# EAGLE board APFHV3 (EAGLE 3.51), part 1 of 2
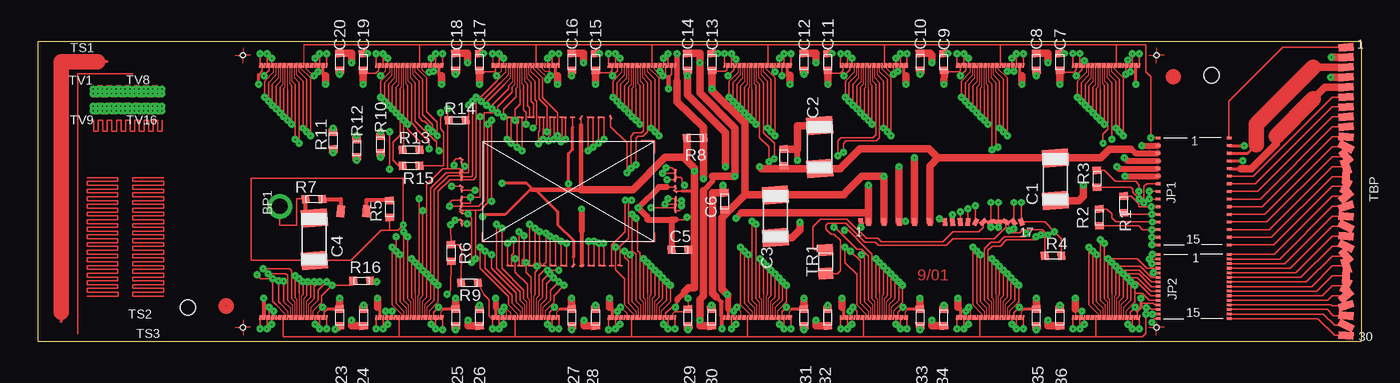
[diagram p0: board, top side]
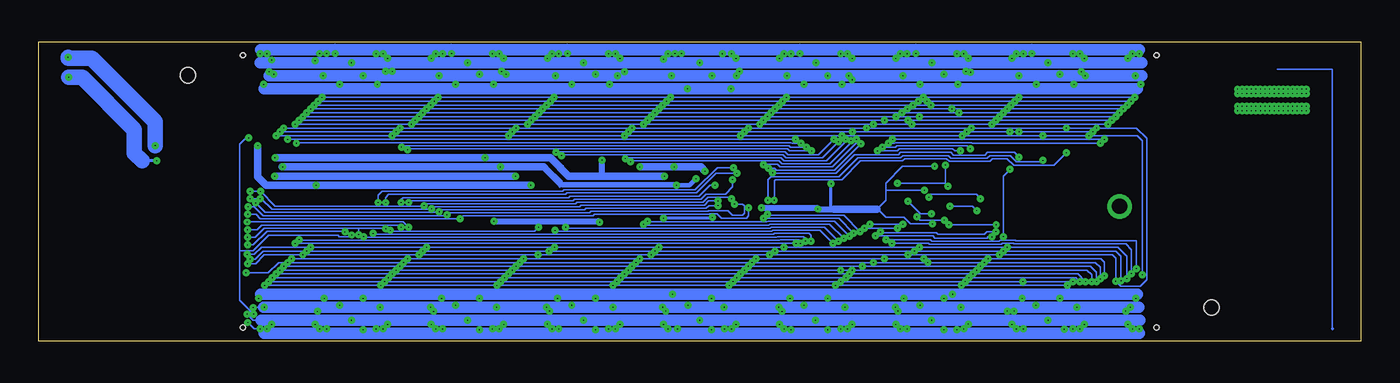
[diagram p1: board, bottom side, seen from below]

Size 86.6 x 19.6 mm. Coordinates in mm from the lower left corner, seen from the top.
Outline: 0,0 86.6,0 86.6,19.6 0,19.6 0,0
Copper layers used: Top, Bottom
Holes 0.3 mm at 73.2,18.7 73.2,0.9 13.4,0.9 13.4,18.7
Holes 1 mm at 76.8,17.4 9.8,2.2
tRestrict: area 77.3,-9.6 to 87.3,3.4

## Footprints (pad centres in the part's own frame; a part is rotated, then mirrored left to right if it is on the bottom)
C_AMS = smd 0.1 x 0.3 rotated 96: 0N 2.225,4.85; 0P 2.075,4.85; 1N 1.525,4.85; 1P 1.375,4.85; 2N -0.275,4.85; 2P -0.425,4.85; 3N -0.975,4.85; 3P -1.125,4.85; 4N -1.675,4.85; 4P -1.825,4.85; 5N -2.375,4.85; 5P -2.525,4.85; 6N -3.075,4.85; 6P -3.225,4.85; 7N -3.775,4.85; 7P -3.925,4.85; 8N -3.875,-4.85; 8P -3.725,-4.85; 9N -3.175,-4.85; 9P -3.025,-4.85; 10N -2.475,-4.85; 10P -2.325,-4.85; 11N -1.775,-4.85; 11P -1.625,-4.85; 12N -1.075,-4.85; 12P -0.925,-4.85; 13N -0.375,-4.85; 13P -0.225,-4.85; 14N 1.425,-4.85; 14P 1.575,-4.85; 15N 2.125,-4.85; 15P 2.275,-4.85 | smd 0.1 x 0.3 rotated 321.2: _0 0.325,-4.85; _2 0.825,4.85 | smd 0.1 x 0.3 rotated 97.6: _0 0.875,-4.85; _2 0.275,4.85 | smd 0.3 x 0.1 rotated 321.2: _1 7,0.025; _3 -7,2.125; _4 -7,0.325; _5 -7,-1.875 | smd 0.3 x 0.1 rotated 97.6: _1 7,0.275; _3 -7,1.875; _4 -7,0.075; _5 -7,-2.125 | smd 0.3 x 0.1 rotated 74.7: B 7,-1.275 | smd 0.3 x 0.1 rotated 209.8: CN -7,-1.225; CP -7,-1.375 | smd 0.3 x 0.1 rotated 97.3: IN 7,-1.025; IP 7,-0.875; ON -7,0.975; OP -7,0.825 | smd 0.3 x 0.1 rotated 75.2: INN -7,-0.825; INP -7,-0.975; N -7,-0.425; P -7,-0.575 | smd 0.3 x 0.1 rotated 73.5: N 7,0.775; P 7,0.925 | smd 0.3 x 0.1 rotated 141.7: N -7,1.375; P -7,1.225 | smd 0.3 x 0.1 rotated 96: N 7,-0.625; P 7,-0.475 | smd 0.3 x 0.1 rotated 253.4:  7,1.175;  7,1.325 | smd 0.1 x 0.3 rotated 28.5:  2.775,4.85 | smd 0.1 x 0.3 rotated 96.7:  2.825,-4.85 | smd 0.1 x 0.3 rotated 73.4:  3.375,-4.85
200 = smd 0.5 x 0.3 rotated 5.8:  0,0
06 = smd 1.15 x 1.7 rotated 4.3:  -1.4,0 | smd 1.15 x 1.7 rotated 4.4:  1.4,0
02 = smd 0.5 x 0.55 rotated 4.3:  -0.55,0 | smd 0.5 x 0.55 rotated 4.4:  0.55,0
GTAIL = smd 0.3 x 0.5 rotated 4.3:  0,0;  7,0 | smd 0.3 x 0.5 rotated 4.4:  0.5,0 | smd 0.3 x 0.5 rotated 4.5:  1.5,0 | smd 0.3 x 0.5 rotated 4.6:  2.5,0 | smd 0.3 x 0.5 rotated 4.7:  3.5,0;  4.5,0 | smd 0.3 x 0.5 rotated 4.8:  5.5,0 | smd 0.3 x 0.5 rotated 4.9:  6,0 | smd 0.3 x 0.5 rotated 5:  6.5,0 | smd 0.3 x 0.5 rotated 26.8:  7.5,0 | smd 0.3 x 0.5 rotated 49.3:  8,0 | smd 0.3 x 0.5 rotated 71.8:  8.5,0 | smd 0.3 x 0.5 rotated 94.3:  9,0 | smd 0.3 x 0.5 rotated 116.8:  9.5,0 | smd 0.3 x 0.5 rotated 139.3:  10,0 | smd 0.3 x 0.5 rotated 161.8:  10.5,0
BP30 = smd 1 x 0.5 rotated 4.3:  0,9.425;  0,3.575 | smd 1 x 0.5 rotated 4.4:  0,8.775;  0,-2.925 | smd 1 x 0.5 rotated 4.5:  0,8.125;  0,-9.425 | smd 1 x 0.5 rotated 4.6:  0,7.475 | smd 1 x 0.5 rotated 4.7:  0,6.825;  0,6.175 | smd 1 x 0.5 rotated 4.8:  0,5.525 | smd 1 x 0.5 rotated 4.9:  0,4.875 | smd 1 x 0.5 rotated 5:  0,4.225 | smd 1 x 0.5 rotated 26.8:  0,2.925 | smd 1 x 0.5 rotated 49.3:  0,2.275 | smd 1 x 0.5 rotated 71.8:  0,1.625 | smd 1 x 0.5 rotated 94.3:  0,0.975 | smd 1 x 0.5 rotated 116.8:  0,0.325 | smd 1 x 0.5 rotated 139.3:  0,-0.325 | smd 1 x 0.5 rotated 161.8:  0,-0.975 | smd 1 x 0.5 rotated 184.3:  0,-1.625 | smd 1 x 0.5 rotated 206.8:  0,-2.275 | smd 1 x 0.5 rotated 26.9:  0,-3.575 | smd 1 x 0.5 rotated 49.4:  0,-4.225 | smd 1 x 0.5 rotated 71.9:  0,-4.875 | smd 1 x 0.5 rotated 94.4:  0,-5.525 | smd 1 x 0.5 rotated 116.9:  0,-6.175 | smd 1 x 0.5 rotated 139.4:  0,-6.825 | smd 1 x 0.5 rotated 161.9:  0,-7.475 | smd 1 x 0.5 rotated 184.4:  0,-8.125 | smd 1 x 0.5 rotated 206.9:  0,-8.775
-I = smd 0.1 x 0.3 rotated 5.8: 0 1.525,0; 0 3.025,0; 0 4.525,0; 1 1.675,0; 1 3.175,0; 1 4.675,0; 2 1.825,0; 2 3.325,0; 2 4.825,0; 3 1.975,0; 3 3.475,0; 3 4.975,0; 4 2.125,0; 4 3.625,0; 4 5.125,0; 5 2.275,0; 5 3.775,0; 5 5.275,0; 6 2.425,0; 6 3.925,0; 6 5.425,0; 7 2.575,0; 7 4.075,0; 7 5.575,0; 8 2.725,0; 8 4.225,0; 8 5.725,0; 9 2.875,0; 9 4.375,0; 9 5.875,0
-SP = smd 0.5 x 0.8 rotated 5.8:  0,0
ACK15C = smd 0.3 x 0.2 rotated 5.8: 0 4.65,0.75; 0 4.65,-0.75; 0 4.65,-2.25; 1 0,0.45; 1 0,-1.05; 2 4.65,0.45; 2 4.65,-1.05; 3 0,0.15; 3 0,-1.35; 4 4.65,0.15; 4 4.65,-1.35; 5 0,-0.15; 5 0,-1.65; 6 4.65,-0.15; 6 4.65,-1.65; 7 0,-0.45; 7 0,-1.95; 8 4.65,-0.45; 8 4.65,-1.95; 9 0,-0.75; 9 0,-2.25;  0,1.95;  4.65,1.95;  0,1.65;  4.65,1.65;  0,1.35;  4.65,1.35;  0,1.05;  4.65,1.05;  0,0.75
ACK15 = smd 0.3 x 0.2 rotated 5.8: 0 4.65,1.5; 0 4.65,-1; 0 4.65,-3.5; 1 0,1; 1 0,-1.5; 2 4.65,1; 2 4.65,-1.5; 3 0,0.5; 3 0,-2; 4 4.65,0.5; 4 4.65,-2; 5 0,0; 5 0,-2.5; 6 4.65,0; 6 4.65,-2.5; 7 0,-0.5; 7 0,-3; 8 4.65,-0.5; 8 4.65,-3; 9 0,-1; 9 0,-3.5;  0,3.5;  4.65,3.5;  0,3;  4.65,3;  0,2.5;  4.65,2.5;  0,2;  4.65,2;  0,1.5
03 = smd 0.75 x 0.95 rotated 4.4:  0.775,0 | smd 0.75 x 0.95 rotated 4.3:  -0.775,0

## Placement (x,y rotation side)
BARE_DIE  MCC_AMS  [C_AMS]  34.7,9.8 0 top
BP1  SENSOR  [200]  15.82,8.83 270 top
C1  4.7  [06]  66.57,10.6 270 top
C2  4.7  [06]  51.15,12.7 90 top
C3  4.7  [06]  48.25,8.18 90 top
C4  .001uF  [06]  18.07,6.68 270 top
C5  0.1 uF  [02]  42,5.98 180 top
C6  0.1  [02]  44.92,9.15 270 top
C7  0.1  [02]  66.88,18.27 90 top
C8  0.1  [02]  65.32,18.27 270 top
C9  0.1  [02]  59.27,18.27 90 top
C10  0.1  [02]  57.72,18.27 270 top
C11  0.1  [02]  51.67,18.27 90 top
C12  0.1  [02]  50.12,18.27 270 top
C13  0.1  [02]  44.1,18.27 90 top
C14  0.1  [02]  42.5,18.27 270 top
C15  0.1  [02]  36.47,18.27 90 top
C16  0.1  [02]  34.92,18.27 270 top
C17  0.1  [02]  28.87,18.27 90 top
C18  0.1  [02]  27.32,18.27 270 top
C19  0.1  [02]  21.27,18.27 90 top
C20  0.1  [02]  19.72,18.27 270 top
C21  0.1  [02]  48.8,12.03 90 top
C23  0.1  [02]  19.72,1.55 270 top
C24  0.1  [02]  21.3,1.55 90 top
C25  0.1  [02]  27.32,1.55 270 top
C26  0.1  [02]  28.87,1.55 90 top
C27  0.1  [02]  34.92,1.55 270 top
C28  0.1  [02]  36.47,1.55 90 top
C29  0.1  [02]  42.52,1.55 270 top
C30  0.1  [02]  44.07,1.55 90 top
C31  0.1  [02]  50.12,1.55 270 top
C32  0.1  [02]  51.67,1.55 90 top
C33  0.1  [02]  57.72,1.55 270 top
C34  0.1  [02]  59.27,1.55 90 top
C35  0.1  [02]  65.32,1.55 270 top
C36  0.1  [02]  66.88,1.55 90 top
CN_PT_  PIGTAIL  [GTAIL]  53.85,7.8 0 top
CN_T  T_BP30  [BP30]  85.6,9.8 0 top
FE-0  FE-I  [-I]  73.6,18.05 180 top
FE-1  FE-I  [-I]  66,18.05 180 top
FE-2  FE-I  [-I]  58.4,18.05 180 top
FE-3  FE-I  [-I]  50.8,18.05 180 top
FE-4  FE-I  [-I]  43.2,18.05 180 top
FE-5  FE-I  [-I]  35.6,18.05 180 top
FE-6  FE-I  [-I]  28,18.05 180 top
FE-7  FE-I  [-I]  20.4,18.05 180 top
FE-8  FE-I  [-I]  13,1.55 0 top
FE-9  FE-I  [-I]  20.6,1.55 0 top
FE-10  FE-I  [-I]  28.2,1.55 0 top
FE-11  FE-I  [-I]  35.8,1.55 0 top
FE-12  FE-I  [-I]  43.4,1.55 0 top
FE-13  FE-I  [-I]  51,1.55 0 top
FE-14  FE-I  [-I]  58.6,1.55 0 top
FE-15  FE-I  [-I]  66.2,1.55 0 top
HV_PT1  VDET  [-SP]  19.8,8.5 180 top
HV_PT2  VDET_ret  [-SP]  21.47,8.5 180 top
JP2_  JPACK15C  [ACK15C]  73.3,3.73 0 top
JPA_  JPACK15  [ACK15]  73.3,9.8 0 top
R1  Zin  [02]  71.05,8.95 270 top
R2  Zin  [02]  69.45,8.1 90 top
R3  Zout  [02]  69.3,10.62 270 top
R4  Zin  [02]  66.42,5.6 180 top
R5  1Ok  [02]  23,8.65 90 top
R6  *2  [02]  27.02,5.78 90 top
R7  10k  [02]  18.05,9.3 0 top
R8  0  [02]  43,13.3 180 top
R9  *2  [02]  28.22,3.83 180 top
R10  *3  [02]  22.4,12.88 90 top
R11  *3  [02]  19.3,13.12 90 top
R12  *3  [02]  20.85,12.62 90 top
R13  110  [02]  24.4,12.53 180 top
R14  110  [02]  27.42,14.45 0 top
R15  110  [02]  24.4,11.48 0 top
R16  110  [02]  21.17,3.95 180 top
TR1  NTC 10k  [03]  51.55,5.2 90 top

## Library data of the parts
BARE_DIE BP1 C1-C21 C23-C36 CN_PT_ CN_T FE-0 FE-1-FE-15 HV_PT1 HV_PT2 JP2_ JPA_ R1-R16 TR1 = 1X

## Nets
AGND: C3. C6. C7. C9. C11. C13. C15. C17. C19. C23. C25. C27. C29. C31. C33. C35. CN_PT_. FE-0.0 FE-0.3 FE-0.6 FE-0.9 FE-1.0 FE-1.3 FE-1.6 FE-1.9 FE-2.0 FE-2.3 FE-2.6 FE-2.9 FE-3.0 FE-3.3 FE-3.6 FE-3.9 FE-4.0 FE-4.3 FE-4.6 FE-4.9 FE-5.0 FE-5.3 FE-5.6 FE-5.9 FE-6.0 FE-6.3 FE-6.6 FE-6.9 FE-7.0 FE-7.3 FE-7.6 FE-7.9 FE-8.0 FE-8.3 FE-8.6 FE-8.9 FE-9.0 FE-9.3 FE-9.6 FE-9.9 FE-10.0 FE-10.3 FE-10.6 FE-10.9 FE-11.0 FE-11.3 FE-11.6 FE-11.9 FE-12.0 FE-12.3 FE-12.6 FE-12.9 FE-13.0 FE-13.3 FE-13.6 FE-13.9 FE-14.0 FE-14.3 FE-14.6 FE-14.9 FE-15.0 FE-15.3 FE-15.6 FE-15.9 JP2_.9 JPA_. R8. R9.
CCK: FE-0.1 FE-1.1 FE-2.1 FE-3.1 FE-4.1 FE-5.1 FE-6.1 FE-7.1 FE-8.1 FE-9.1 FE-10.1 FE-11.1 FE-12.1 FE-13.1 FE-14.1 FE-15.1 JP2_. R12.
CKN: BARE_DIE. CN_PT_. JPA_.7 R4.
CKP: BARE_DIE. CN_PT_. JPA_.9 R4.
DA: FE-0.2 FE-1.2 FE-2.2 FE-3.2 FE-4.2 FE-5.2 FE-6.2 FE-7.2 FE-8.2 FE-9.2 FE-10.2 FE-11.2 FE-12.2 FE-13.2 FE-14.2 FE-15.2 JP2_. R10.
DCIN: BARE_DIE.N CN_PT_. JPA_.3 R2.
DCIP: BARE_DIE.P CN_PT_. JPA_.5 R2.
DETV: BP1. C4. R7.
DGND: BARE_DIE._0 BARE_DIE._1 BARE_DIE._2 BARE_DIE._3 BARE_DIE._4 BARE_DIE._5 C1. C2. C5. C8. C10. C12. C14. C16. C18. C20. C21. C24. C26. C28. C30. C32. C34. C36. CN_PT_. FE-0.4 FE-0.5 FE-0.6 FE-0.7 FE-0.8 FE-0.9 FE-1.4 FE-1.5 FE-1.7 FE-1.8 FE-1.9 FE-2.4 FE-2.5 FE-2.6 FE-2.8 FE-2.9 FE-3.4 FE-3.5 FE-3.8 FE-3.9 FE-4.4 FE-4.5 FE-4.6 FE-4.7 FE-4.9 FE-5.4 FE-5.5 FE-5.7 FE-5.9 FE-6.4 FE-6.5 FE-6.6 FE-6.9 FE-7.4 FE-7.5 FE-7.9 FE-8.4 FE-8.5 FE-8.6 FE-8.7 FE-8.8 FE-9.4 FE-9.5 FE-9.7 FE-9.8 FE-10.4 FE-10.5 FE-10.6 FE-10.8 FE-11.4 FE-11.5 FE-11.8 FE-12.4 FE-12.5 FE-12.6 FE-12.7 FE-13.4 FE-13.5 FE-13.7 FE-14.4 FE-14.5 FE-14.6 FE-15.4 FE-15.5 JP2_.5 JPA_. R8.
DTO0N: BARE_DIE.N CN_PT_. JPA_.7 R3.
DTO0P: BARE_DIE.P CN_PT_. JPA_.5 R3.
FE-0N: BARE_DIE.0N FE-0.4
FE-0P: BARE_DIE.0P FE-0.5
FE-1N: BARE_DIE.1N FE-1.4
FE-1P: BARE_DIE.1P FE-1.5
FE-2N: BARE_DIE.2N FE-2.4
FE-2P: BARE_DIE.2P FE-2.5
FE-3N: BARE_DIE.3N FE-3.4
FE-3P: BARE_DIE.3P FE-3.5
FE-4N: BARE_DIE.4N FE-4.4
FE-4P: BARE_DIE.4P FE-4.5
FE-5N: BARE_DIE.5N FE-5.4
FE-5P: BARE_DIE.5P FE-5.5
FE-6N: BARE_DIE.6N FE-6.4
FE-6P: BARE_DIE.6P FE-6.5
FE-7N: BARE_DIE.7N FE-7.4
FE-7P: BARE_DIE.7P FE-7.5
FE-8N: BARE_DIE.8N FE-8.4
FE-8P: BARE_DIE.8P FE-8.5
FE-9N: BARE_DIE.9N FE-9.4
FE-9P: BARE_DIE.9P FE-9.5
FE-10N: BARE_DIE.10N FE-10.4
FE-10P: BARE_DIE.10P FE-10.5
FE-11N: BARE_DIE.11N FE-11.4
FE-11P: BARE_DIE.11P FE-11.5
FE-12N: BARE_DIE.12N FE-12.4
FE-12P: BARE_DIE.12P FE-12.5
FE-13N: BARE_DIE.13N FE-13.4
FE-13P: BARE_DIE.13P FE-13.5
FE-14N: BARE_DIE.14N FE-14.4
FE-14P: BARE_DIE.14P FE-14.5
FE-15N: BARE_DIE.15N FE-15.4
FE-15P: BARE_DIE.15P FE-15.5
HV_GUARD: C4. R5. R6. R9.
LD: FE-0.3 FE-1.3 FE-2.3 FE-3.3 FE-4.3 FE-5.3 FE-6.3 FE-7.3 FE-8.3 FE-9.3 FE-10.3 FE-11.3 FE-12.3 FE-13.3 FE-14.3 FE-15.3 JP2_. R11.
LV1N: BARE_DIE.N FE-0.0 FE-1.0 FE-2.0 FE-3.0 FE-4.0 FE-5.0 FE-6.0 FE-7.0 FE-8.0 FE-9.0 FE-10.0 FE-11.0 FE-12.0 FE-13.0 FE-14.0 FE-15.0 JP2_.5 R14.
LV1P: BARE_DIE.P FE-0.1 FE-1.1 FE-2.1 FE-3.1 FE-4.1 FE-5.1 FE-6.1 FE-7.1 FE-8.1 FE-9.1 FE-10.1 FE-11.1 FE-12.1 FE-13.1 FE-14.1 FE-15.1 JP2_.7 R14.
N$2: CN_T. JPA_.0
N$4: CN_T. JP2_.
N$5: CN_T. JP2_.
N$6: CN_T. JP2_.
N$7: CN_T. JPA_.0
N$8: CN_T. JP2_.
N$9: CN_T. JP2_.0
N$10: CN_T. JPA_.2
N$11: CN_T. JP2_.2
N$12: CN_T. JP2_.4
N$13: CN_T. JP2_.6
N$14: CN_T. JPA_.6
N$15: CN_T. JPA_.4
N$16: CN_T. JPA_.6
N$17: CN_T. JPA_.8
N$18: CN_T. JPA_.8
N$19: CN_T. JPA_.0
N$20: CN_T. JPA_.4
N$21: CN_T. JPA_.
N$22: CN_T. JPA_.
N$23: CN_T. JPA_.
N$24: CN_T. JPA_.
N$25: CN_T. JPA_.2
N$26: CN_T. JP2_.8
N$27: CN_T. JP2_.0
N$28: CN_T. JP2_.2
N$29: CN_T. JP2_.6
N$30: CN_T. JP2_.8
N$31: BARE_DIE. R10.
N$32: CN_T. JP2_.4
N$33: CN_T. JP2_.0
N$34: BARE_DIE. R11.
N$35: BARE_DIE. R12.
NTC: CN_PT_. TR1.
NTC_RET: CN_PT_. TR1.
RSIB: BARE_DIE.B CN_PT_. JPA_.3
STRIN: BARE_DIE.IN CN_PT_. JPA_.1 R1.
STRIP: BARE_DIE.IP CN_PT_. JPA_.9 R1.
STRN: BARE_DIE.ON FE-0.2 FE-1.2 FE-2.2 FE-3.2 FE-4.2 FE-5.2 FE-6.2 FE-7.2 FE-8.2 FE-9.2 FE-10.2 FE-11.2 FE-12.2 FE-13.2 FE-14.2 FE-15.2 JP2_.9 R16.
STRP: BARE_DIE.OP FE-0.3 FE-1.3 FE-2.3 FE-3.3 FE-4.3 FE-5.3 FE-6.3 FE-7.3 FE-8.3 FE-9.3 FE-10.3 FE-11.3 FE-12.3 FE-13.3 FE-14.3 FE-15.3 JP2_.1 R16.
SYNCN: BARE_DIE.CN FE-0.6 FE-1.6 FE-2.6 FE-3.6 FE-4.6 FE-5.6 FE-6.6 FE-7.6 FE-8.6 FE-9.6 FE-10.6 FE-11.6 FE-12.6 FE-13.6 FE-14.6 FE-15.6 JP2_. R13.
SYNCP: BARE_DIE.CP FE-0.7 FE-1.7 FE-2.7 FE-3.7 FE-4.7 FE-5.7 FE-6.7 FE-7.7 FE-8.7 FE-9.7 FE-10.7 FE-11.7 FE-12.7 FE-13.7 FE-14.7 FE-15.7 JP2_. R13.
VCAL: CN_PT_. FE-0.0 FE-1.0 FE-2.0 FE-3.0 FE-4.0 FE-5.0 FE-6.0 FE-7.0 FE-8.0 FE-9.0 FE-10.0 FE-11.0 FE-12.0 FE-13.0 FE-14.0 FE-15.0 JPA_.
VDD: C2. C8. C10. C12. C14. C16. C18. C20. C21. C24. C26. C28. C30. C32. C34. C36. CN_PT_. FE-0.4 FE-0.5 FE-1.4 FE-1.5 FE-2.4 FE-2.5 FE-3.4 FE-3.5 FE-4.4 FE-4.5 FE-5.4 FE-5.5 FE-6.4 FE-6.5 FE-7.4 FE-7.5 FE-8.4 FE-8.5 FE-9.4 FE-9.5 FE-10.4 FE-10.5 FE-11.4 FE-11.5 FE-12.4 FE-12.5 FE-13.4 FE-13.5 FE-14.4 FE-14.5 FE-15.4 FE-15.5 JP2_.7 JPA_.
VDD_AMS: BARE_DIE._0 BARE_DIE._1 BARE_DIE._2 BARE_DIE._3 BARE_DIE._4 BARE_DIE._5 C1. C5. CN_PT_. JPA_.
VDDA: C3. C6. C7. C9. C11. C13. C15. C17. C19. C23. C25. C27. C29. C31. C33. C35. CN_PT_. FE-0.1 FE-0.2 FE-0.7 FE-0.8 FE-1.1 FE-1.2 FE-1.7 FE-1.8 FE-2.1 FE-2.2 FE-2.7 FE-2.8 FE-3.1 FE-3.2 FE-3.7 FE-3.8 FE-4.1 FE-4.2 FE-4.7 FE-4.8 FE-5.1 FE-5.2 FE-5.7 FE-5.8 FE-6.1 FE-6.2 FE-6.7 FE-6.8 FE-7.1 FE-7.2 FE-7.7 FE-7.8 FE-8.1 FE-8.2 FE-8.7 FE-8.8 FE-9.1 FE-9.2 FE-9.7 FE-9.8 FE-10.1 FE-10.2 FE-10.7 FE-10.8 FE-11.1 FE-11.2 FE-11.7 FE-11.8 FE-12.1 FE-12.2 FE-12.7 FE-12.8 FE-13.1 FE-13.2 FE-13.7 FE-13.8 FE-14.1 FE-14.2 FE-14.7 FE-14.8 FE-15.1 FE-15.2 FE-15.7 FE-15.8 JP2_.3 JPA_.1 R6.
VDET: HV_PT1. R7.
VDET_RET: HV_PT2. R5.
XCKN: BARE_DIE.INN BARE_DIE.N FE-0.8 FE-1.8 FE-2.8 FE-3.8 FE-4.8 FE-5.8 FE-6.8 FE-7.8 FE-8.8 FE-9.8 FE-10.8 FE-11.8 FE-12.8 FE-13.8 FE-14.8 FE-15.8 JP2_.1 R15.
XCKP: BARE_DIE.INP BARE_DIE.P FE-0.9 FE-1.9 FE-2.9 FE-3.9 FE-4.9 FE-5.9 FE-6.9 FE-7.9 FE-8.9 FE-9.9 FE-10.9 FE-11.9 FE-12.9 FE-13.9 FE-14.9 FE-15.9 JP2_.3 R15.

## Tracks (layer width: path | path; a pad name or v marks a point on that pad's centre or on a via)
AGND  (via drill 0.05 pad 0.2)
  Top 0: v51.95,18.83 C11. | v67.15,18.83 C7. | v29.15,18.83 C17. | v67.15,18.83 C7. | 19.72,0.78 C23. | v27.32,0.75 C25. | v34.92,0.75 C27. | v57.72,0.75 C33. | v65.32,0.75 C35. | 73.25,11.3 JPA_. | v67.15,18.83 C7. | 41.67,18.05 41.67,18.8 v41.82,18.8 | v44.75,0.8 44.75,1.58 | v50.12,0.75 C31. v50.12,0.75
  Top 0.075: v29.72,18.8 FE-5.9
  Top 0.1: v56.88,18.8 56.88,18.05 | v72.07,18.8 72.07,18.05 | v64.47,18.8 64.47,18.05 | FE-0.9 v67.72,18.83 67.72,18.43 | C7. 66.88,18.62 | 68.17,18.15 FE-0.6 v68.17,18.83 | v44.92,18.83 FE-3.9 | v60.12,18.8 FE-1.9 | v52.52,18.8 FE-2.9 | v37.32,18.8 FE-4.9 | v34.07,18.8 34.07,18.05 | v26.47,18.8 26.47,18.05 | v22.12,18.8 FE-6.9 | v71.62,18.8 71.62,18.05 | v64.03,18.8 64.03,18.05 | v56.42,18.8 56.42,18.05 | v60.57,18.8 FE-1.6 | v52.97,18.8 FE-2.6 | v49.27,18.8 49.27,18.05 | v48.82,18.8 48.82,18.05 | v45.38,18.8 FE-3.6 | v41.22,18.8 41.22,18.05 | v37.77,18.8 FE-4.6 | v33.62,18.8 33.62,18.05 | v30.17,18.8 FE-5.6 | v18.87,18.8 18.87,18.05 | v18.42,18.8 18.42,18.05 | v14.52,18.8 FE-7.9 | v14.97,18.8 FE-7.6 | v14.52,0.8 14.52,1.55 | v14.97,0.8 14.97,1.55 | v18.87,0.8 FE-8.9 | v18.42,0.8 FE-8.6 | v22.12,0.8 22.12,1.55 | v22.57,0.8 22.57,1.55 | v26.47,0.75 FE-9.9 | v26.02,0.8 FE-9.6 | v29.72,0.8 29.72,1.55 29.62,1.55 29.5,1.68 29.5,2.73 29.17,3.05 28.77,3.83 | v30.17,0.8 30.17,1.55 | v34.07,0.8 FE-10.9 | v33.62,0.8 FE-10.6 | v37.32,0.75 37.32,1.55 | v37.77,0.8 37.77,1.55 | v45.38,0.8 45.38,1.55 | v41.67,0.8 FE-11.9 | v41.22,0.8 FE-11.6 | 44.75,1.58 44.92,1.55 | v49.27,0.8 FE-12.9 | v48.82,0.8 FE-12.6 | 52.52,1.55 v52.52,0.8 | v52.97,0.8 52.97,1.55 | v56.88,0.8 FE-13.9 | v56.42,0.8 FE-13.6 | v60.12,0.8 60.12,1.55 | v60.57,0.8 60.57,1.55 | v64.03,0.8 FE-14.6 | v64.47,0.8 FE-14.9 | v67.72,0.8 67.72,1.55 | v68.17,0.8 68.17,1.55 | v71.62,0.8 FE-15.6 | v72.07,0.8 FE-15.9 | JP2_.9 73.05,1.48 72.88,1.3 v72.88,1.23 | v26.02,18.8 26.02,18.05 | v22.57,18.8 FE-6.6
  Top 0.2: v67.15,18.83 C7. | v59.55,18.83 C9. | v51.95,18.83 C11. | v36.75,18.83 C15. | v29.15,18.83 C17. | v21.55,18.83 C19. | v19.45,0.78 19.72,0.78 | v27.32,0.75 C25. | v34.92,0.75 C27. | v50.12,0.75 C31. | v57.72,0.75 C33. | v65.32,0.75 C35. | v44.5,18.83 C13. | v42.52,0.75 C29.
  Top 0.25: 44.38,2.9 44.72,2.55 44.72,1.62 44.75,1.6 v44.75,0.8
  Top 0.35: 41.8,15.68 41.82,15.7 | 41.82,17 v41.82,18.8
  Top 0.4: 56.35,7.85 v56.77,7.85 | 44.92,9.7 44.82,9.8 v44.82,10.2 | 73.28,11.3 73.25,11.3 70.7,11.3 v70.6,11.4
  Top 0.5: v56.35,11.4 56.35,7.85 56.35,7.8 | 48.25,6.78 49.32,6.78 49.85,7.3 v49.85,7.78 | v43.55,10.62 43.55,13.3 43.55,14 41.8,15.68 | 41.82,15.7 41.82,17 | v44.82,10.2 44.82,9.7 44.15,9.7 44.15,3.13 44.38,2.9
  Bottom 0: 36.5,0.53 34.07,0.53 v34.07,0.8 33.77,0.78 | 36.5,0.53 36.5,0.65 | 36.5,0.53 37.32,0.53 v37.32,0.75 37.62,0.75 | 22.27,19.08 v22.12,18.8 v22.57,18.8 | 18.72,18.8 18.72,19.08 | 21.55,19.45 21.55,19.08 v21.55,18.83 21.2,19.18 20.85,19.18 20.47,18.8 v18.87,18.8 | 60.5,18.8 60.27,19.08 | 56.72,18.8 56.72,19.08 | 60.5,18.8 60.25,18.83 v59.55,18.83 | v59.55,18.83 59.52,18.8 | 64.32,18.8 64.32,19.08 | 64.32,18.8 64.42,18.8 64.45,18.83 C7. | v60.57,18.8 v64.03,18.8 | v60.57,18.8 60.5,18.8 | v64.03,18.8 64.32,18.8 | v59.55,18.83 59.55,19.45 | v59.55,18.83 59.55,19.08 | v59.55,18.83 v60.12,18.8 60.5,18.8 | v72.07,18.8 71.92,19.08 72.05,19.08 | v29.72,18.8 29.87,19.08 | 26.32,18.8 26.32,19.08 | v29.72,18.8 29.85,18.83 v29.15,18.83 | v29.15,18.83 29.12,18.8 v26.47,18.8 | v26.47,18.8 26.32,18.8 | v29.15,18.83 29.15,19.45 | v29.15,18.83 29.15,19.08 | v29.72,18.8 29.17,18.8 v29.15,18.83 | v29.15,18.83 26.35,18.83 26.32,18.8 | 26.32,18.8 26.1,18.8 | 26.1,18.8 v26.02,18.8 | v26.02,18.8 v22.57,18.8 | v67.15,18.83 67.15,19.45 | v67.15,18.83 67.15,19.08 | 56.85,18.83 v56.88,18.8 56.72,18.8 | v59.55,18.83 56.75,18.83 56.72,18.8 | 67.88,19.08 67.88,18.8 v67.72,18.83 | v67.72,18.83 v67.15,18.83 | v72.07,18.8 68.03,18.8 | v67.72,18.83 67.17,18.8 | v52.52,18.8 52.67,19.08 | v52.52,18.8 52.65,18.83 v51.95,18.83 | v51.95,18.83 51.92,18.8 | v52.97,18.8 v56.42,18.8 | v52.97,18.8 v52.52,18.8 | v56.42,18.8 56.72,18.8 | v51.95,18.83 51.95,19.45 | v51.95,18.83 51.95,19.08 | v52.52,18.8 51.97,18.8 v51.95,18.83 | v51.95,18.83 v49.27,18.8 49.27,19.08 | 41.52,18.8 41.52,19.08 | 41.3,18.8 41.65,18.83 | 41.52,18.8 41.55,18.83 | v37.32,18.8 37.47,19.08 36.75,19.08 v36.75,18.83
  Bottom 0: 33.92,19.08 33.92,18.8 | v37.32,18.8 37.45,18.83 v36.75,18.83 | v36.75,18.83 36.72,18.8 | 41.3,18.8 41.52,18.8 | v41.22,18.8 v37.77,18.8 | 41.3,18.8 v41.22,18.8 | v37.77,18.8 v37.32,18.8 | v36.75,18.83 36.75,19.45 | v37.32,18.8 36.77,18.8 v36.75,18.83 | 33.92,18.8 33.7,18.8 | v33.62,18.8 33.7,18.8 | v33.62,18.8 v30.17,18.8 | v30.17,18.8 30.1,18.8 | 30.1,18.8 v29.72,18.8 | 34.05,18.83 34.02,18.8 33.92,18.8 | v36.75,18.83 33.95,18.83 33.92,18.8 | 14.67,19.08 14.67,18.8 v14.97,18.8 | 18.72,18.8 v18.42,18.8 | v18.42,18.8 v14.97,18.8 | v18.87,0.8 18.72,0.53 | v22.12,0.8 20.52,0.8 20.15,0.43 19.8,0.43 v19.45,0.78 19.35,0.78 19.32,0.8 v18.87,0.8 | v18.87,18.8 18.72,18.8 | 29.85,0.78 29.87,0.8 v30.17,0.8 | 29.77,0.75 29.82,0.75 | 29.77,0.75 v27.32,0.75 v26.47,0.75 26.32,0.8 | v33.62,0.8 v30.17,0.8 | v33.62,0.8 33.92,0.8 33.97,0.75 v34.92,0.75 34.97,0.8 37.47,0.8 | 37.47,0.8 37.45,0.78 | 37.47,0.8 37.55,0.8 | 41.67,0.53 v41.67,0.8 | 44.1,0.53 43.65,0.53 | v41.67,0.8 41.38,0.78 | 44.92,0.53 44.92,0.75 45.22,0.75 | 44.1,0.53 44.1,0.65 | 44.1,0.53 44.42,0.53 44.42,0.68 44.45,0.7 | v41.22,0.8 v37.77,0.8 | v41.67,0.8 v41.22,0.8 | v37.77,0.8 37.47,0.8 | 44.92,0.8 45.05,0.78 | 44.92,0.8 45.15,0.8 | 49.12,0.8 49.27,0.53 v49.27,0.8 | 51.7,0.53 50.12,0.53 v50.12,0.75 52.75,0.8 52.67,0.8 | 49.12,0.8 48.97,0.78 | 51.7,0.53 51.7,0.65 | 51.7,0.53 52.52,0.53 v52.52,0.8 52.82,0.75 | v48.82,0.8 v45.38,0.8 | 49.12,0.8 v48.82,0.8 | v45.38,0.8 44.92,0.8 | 52.67,0.8 52.65,0.78 | 56.88,0.53 56.72,0.8 | 56.88,0.53 59.3,0.53 | 56.72,0.8 56.57,0.78 | 60.12,0.53 60.12,0.75 60.42,0.75 | 59.3,0.53 59.3,0.65 | 59.3,0.53 60.12,0.53 | v52.97,0.8 v56.42,0.8 | v56.42,0.8 56.72,0.8 | v52.97,0.8 52.67,0.8
  Bottom 0: 60.27,0.8 60.25,0.78 | 60.27,0.8 60.35,0.8 | 56.72,0.8 v57.72,0.75 | 64.47,0.53 64.32,0.8 | 64.47,0.53 66.9,0.53 | 64.32,0.8 64.17,0.78 | 67.72,0.53 67.72,0.75 68.03,0.75 | 66.9,0.53 66.9,0.65 | 67.72,0.53 66.9,0.53 | v60.57,0.8 v64.03,0.8 | v64.03,0.8 64.32,0.8 | v60.57,0.8 60.27,0.8 | 67.88,0.8 67.85,0.78 | 67.88,0.8 67.95,0.8 v65.32,0.75 64.32,0.8 | v68.17,0.8 67.88,0.8 | v68.17,0.8 v71.62,0.8 | v71.62,0.8 71.92,0.8 | 14.67,0.53 v14.52,0.8 v14.97,0.8 | v14.97,0.8 v18.42,0.8 v18.87,0.8 | 42.52,0.53 v41.67,0.8 | 42.52,0.53 43.3,0.58 | 45.02,19.08 45.07,19.02 | v56.35,11.4 53.62,11.4 53.6,11.43 53.55,11.43 | 56.5,19.08 v56.42,18.8 | v72.07,18.8 v71.62,18.8 | 41.67,19.08 v41.82,18.8 41.67,19.05 41.7,19.08 | 44.5,19.08 v44.5,18.83 v44.92,18.83 45.3,18.83 45.3,19.08 | 48.9,19.08 48.9,18.8 | 41.3,19.08 41.3,18.8 | v67.72,18.83 v68.17,18.83 68.1,19.08 | 33.7,19.08 33.7,18.8 | 37.7,19.08 v37.77,18.8 | 30.1,18.8 30.1,19.08 | 26.47,19.08 v26.47,18.8 | 26.1,18.8 26.02,19.08 v26.02,18.8 | 22.5,19.08 v22.57,18.8 | 64.03,19.08 v64.03,18.8 | 64.47,19.08 v64.47,18.8 | 60.57,19.08 v60.57,18.8 | 52.97,19.08 v52.97,18.8 | 48.82,19.08 v48.82,18.8 | 45.38,19.08 v45.38,18.8 | 41.22,19.08 v41.22,18.8 | v33.62,18.8 v34.07,18.8 34.07,19.08 | 30.17,19.08 v30.17,18.8 | 18.87,19.08 v18.87,18.8 | 18.42,19.08 v18.42,18.8 | 14.52,19.08 v14.52,18.8 | 14.97,19.08 v14.97,18.8 | 14.97,0.53 v14.97,0.8 | 18.87,0.53 v18.87,0.8 | 22.57,0.53 v22.57,0.8 | 26.02,0.53 v26.02,0.8 | 29.77,0.75 29.77,0.58 29.72,0.53 v29.72,0.8 | 30.17,0.53 v30.17,0.8 | 33.62,0.53 v33.62,0.8 | 37.77,0.53 v37.77,0.8 | 45.38,0.53 v45.38,0.8 | 41.22,0.53 v41.22,0.8 | 42.52,0.53 v42.52,0.75 | 44.92,0.8 v44.75,0.8 44.75,0.53
  Bottom 0: 48.82,0.53 v48.82,0.8 | 52.97,0.53 v52.97,0.8 | 56.88,0.53 v56.88,0.8 | v56.42,0.8 56.42,0.55 56.45,0.53 | 60.12,0.53 v60.12,0.8 | 60.57,0.53 v60.57,0.8 | 64.03,0.53 v64.03,0.8 | 64.47,0.53 v64.47,0.8 | 67.72,0.53 v67.72,0.8 | 68.17,0.53 v68.17,0.8 | v71.62,0.8 71.62,0.53 72.07,0.53 v72.07,0.8
  Bottom 0.1: 71.92,0.8 v72.07,0.8 72.45,0.8 v72.88,1.23
  Bottom 0.2: 44.8,10.35 52.47,10.35 52.5,10.38 | 53.6,11.43 53.6,11.28 52.45,10.12 | 53.55,11.43 53.32,11.43 52.35,10.45
  Bottom 0.3: 53.52,11.4 52.5,10.38 52.32,10.2 v44.82,10.2 43.97,10.2 v43.55,10.62
  Bottom 0.4: v49.85,7.78 49.92,7.85 v56.77,7.85
  Bottom 0.5: 70.62,11.4 v70.6,11.4 v56.35,11.4 53.52,11.4
  Bottom 0.75: 64.47,0.53 66.62,0.53 | 33.62,0.53 34.07,0.53 37.32,0.53 37.77,0.53 | 22.57,0.53 18.87,0.53 14.97,0.53 14.52,0.53 | 14.52,19.08 14.97,19.08 18.42,19.08 18.87,19.08 21.55,19.08 22.27,19.08 22.5,19.08 26.02,19.08 26.47,19.08 30.1,19.08 30.17,19.08 33.7,19.08 33.92,19.08 34.07,19.08 37.47,19.08 37.7,19.08 41.22,19.08 41.3,19.08 41.67,19.08 41.7,19.08 44.5,19.08 45.02,19.08 45.3,19.08 45.38,19.08 48.82,19.08 48.9,19.08 49.27,19.08 52.97,19.08 56.5,19.08 60.57,19.08 64.03,19.08 64.47,19.08 68.1,19.08 72.05,19.08 | 42.52,0.53 41.67,0.53 41.22,0.53 | 71.8,0.53 71.62,0.53 68.17,0.53 67.72,0.53 64.47,0.53 | 22.57,0.53 26.02,0.53 29.72,0.53 30.17,0.53 33.62,0.53 | 22.57,0.53 22.12,0.53 | 52.52,0.53 50.12,0.53 | 37.77,0.53 33.62,0.53 | 42.52,0.53 43.65,0.53 44.42,0.53 44.75,0.53 44.92,0.53 45.38,0.53 48.82,0.53 49.27,0.53 50.12,0.53 | 42.52,0.53 41.22,0.53 | 41.22,0.53 37.77,0.53 | 50.12,0.53 52.97,0.53 56.45,0.53 56.88,0.53 60.12,0.53 60.57,0.53 64.03,0.53 64.47,0.53
CCK  (via drill 0.05 pad 0.2)
  Top 0.075: 17.82,17.23 17.22,17.83 17.22,18.05 | 25.42,17.23 24.82,17.83 24.82,18.05 | 33.02,17.23 32.42,17.83 32.42,18.05 | 40.62,17.23 40.02,17.83 40.02,18.05 | 48.22,17.23 47.62,17.83 47.62,18.05 | 55.82,17.23 55.22,17.83 55.22,18.05 | 63.42,17.23 62.82,17.83 62.82,18.05 | 71.03,17.23 70.42,17.83 70.42,18.05 | 15.57,2.38 16.17,1.78 16.17,1.55 | 23.17,2.38 23.77,1.78 23.77,1.55 | 30.77,2.38 31.37,1.78 31.37,1.55 | 38.38,2.38 38.97,1.78 38.97,1.55 | 53.57,2.38 54.17,1.78 54.17,1.55 | 61.17,2.38 61.77,1.78 61.77,1.55 | 68.78,2.38 69.38,1.78 69.38,1.55 | 45.97,2.38 46.57,1.78 46.57,1.55
  Top 0.1: v28.92,6.15 28.92,4.78 30.77,2.93 30.77,2.38 | v34,13.45 34,14.95 33.02,15.93 33.02,17.23 | v14.32,4.35 14.57,4.1 v15.35,4.1 15.35,2.6 15.57,2.38 | v72.92,5.68 73.3,5.68 | v20.85,13.45 R12. | v17.82,13.45 17.82,17.23 | 25.42,17.23 25.42,15.03 26.12,14.33 v26.12,13.45 | v40.62,13.45 40.62,17.23 | v48.22,13.45 48.22,17.23 | v55.82,13.45 55.82,17.23 | v63.42,13.45 63.42,17.23 | v71.03,13.45 71.03,17.23 | v23.17,6.15 23.17,2.38 | 38.38,2.38 38.38,4.1 37.8,4.68 v37.8,6.15 | 53.57,2.38 53.57,4.38 52.8,5.15 v52.8,6.15 | v61.17,6.15 61.17,2.38 | v68.78,6.15 68.78,2.38 | v45.97,6.15 45.97,2.38
  Bottom 0.1: v71.03,13.45 v63.42,13.45 v55.82,13.45 v48.22,13.45 v40.62,13.45 v34,13.45 v26.12,13.45 v20.85,13.45 v17.82,13.45 14.65,13.45 14.32,13.12 v14.32,4.35 | v72.92,5.68 72.45,5.68 71.97,6.15 v68.78,6.15 v61.17,6.15 v52.8,6.15 v45.97,6.15 v37.8,6.15 v28.92,6.15 v23.17,6.15 15.92,6.15 15.35,5.58 v15.35,4.1
CKN  (via drill 0.05 pad 0.2)
  Top 0.1: v63.85,9.08 63.85,7.8 v63.85,7.35 | v72.9,6.8 JPA_.7 | 41.7,10.98 v40.88,10.98 | R4. 65.88,6.73 v65.62,6.98
  Bottom 0.1: v72.9,6.8 72.4,6.8 71.8,7.4 65.62,7.4 | v40.88,10.98 42.22,10.98 43.5,9.7 52,9.7 52.1,9.6 63.65,9.6 63.85,9.4 v63.85,9.08 | 65.62,7.4 v65.62,6.98 | v63.85,7.35 63.9,7.4 65.62,7.4
CKP  (via drill 0.05 pad 0.2)
  Top 0.1: v64.35,9.08 CN_PT_. 65.88,7.8 v66.53,7.15 66.97,6.7 66.97,5.6 | v72.9,6.3 JPA_.9 | 41.7,11.12 41.47,11.35 v41.1,11.35
  Bottom 0.1: v72.9,6.3 72.53,6.3 71.62,7.2 66.57,7.2 v66.53,7.15 | v41.1,11.35 42.15,11.35 43.6,9.9 52.17,9.9 52.27,9.8 64.1,9.8 64.35,9.55 v64.35,9.08
DA  (via drill 0.05 pad 0.2)
  Top 0.075: 17.57,17.12 17.07,17.62 17.07,18.05 | 25.17,17.12 24.67,17.62 24.67,18.05 | 32.77,17.12 32.27,17.62 32.27,18.05 | 40.38,17.12 39.88,17.62 39.88,18.05 | 47.97,17.12 47.47,17.62 47.47,18.05 | 55.57,17.12 55.07,17.62 55.07,18.05 | 63.17,17.12 62.67,17.62 62.67,18.05 | 70.78,17.12 70.28,17.62 70.28,18.05 | 15.82,2.48 16.32,1.98 16.32,1.55 | 23.42,2.48 23.92,1.98 23.92,1.55 | 31.02,2.48 31.52,1.98 31.52,1.55 | 38.62,2.48 39.12,1.98 39.12,1.55 | 53.82,2.48 54.32,1.98 54.32,1.55 | 61.42,2.48 61.92,1.98 61.92,1.55 | 69.03,2.48 69.53,1.98 69.53,1.55 | 46.22,2.48 46.72,1.98 46.72,1.55
  Top 0.1: v29.25,5.9 29.25,4.78 31.02,3 31.02,2.48 | v23,11.25 v23,13.7 | v72.72,5.38 73.3,5.38 | v22.4,13.7 R10. | v17.57,13.7 17.57,17.12 | v25.82,13.7 25.82,14.18 25.17,14.83 25.17,17.12 | v33.3,13.7 33.3,15.33 32.77,15.85 32.77,17.12 | v40.38,13.7 40.38,17.12 | v47.97,13.7 47.97,17.12 | v55.57,13.7 55.57,17.12 | v63.17,13.7 63.17,17.12 | v70.78,13.7 70.78,17.12 | 15.72,3.98 v15.72,3.95 15.72,2.58 15.82,2.48 | 23.42,2.48 v23.42,5.9 v23.42,6.85 | 38.62,2.48 38.62,5.25 38.38,5.5 v38.38,5.9 | 53.82,2.48 53.82,5.25 v53.17,5.9 | v61.42,5.9 61.42,2.48 | v69.03,5.9 69.03,2.48 | v46.22,5.9 46.22,2.48
  Bottom 0.1: v17.57,13.7 v22.4,13.7 v23,13.7 v25.82,13.7 v33.3,13.7 v40.38,13.7 v47.97,13.7 v55.57,13.7 v63.17,13.7 v70.78,13.7 | v72.72,5.38 72.4,5.38 71.88,5.9 v69.03,5.9 v61.42,5.9 v53.17,5.9 v46.22,5.9 v38.38,5.9 v29.25,5.9 v23.42,5.9 16.05,5.9 15.72,5.58 v15.72,3.95 | v23,11.25 23,11.23 23.42,10.8 v23.42,6.85
DCIN  (via drill 0.05 pad 0.2)
  Top 0.1: v62.35,9.08 62.35,7.8 v62.35,7.45 | JPA_.3 v72.92,7.8 72.9,7.83 70.53,7.83 70.28,8.08 70.28,8.33 69.95,8.65 R2. | 41.7,10.58 v41.15,10.58
  Bottom 0.1: v62.35,7.45 62.7,7.8 v72.92,7.8 | v41.15,10.58 41.15,10.1 41.62,9.62 42.9,9.62 43.22,9.3 51.5,9.3 51.6,9.2 62.22,9.2 v62.35,9.08
DCIP  (via drill 0.05 pad 0.2)
  Top 0.1: v62.85,9.08 62.85,7.8 v62.85,7.45 | JPA_.5 v72.9,7.3 72.28,7.3 72.03,7.55 69.45,7.55 | 41.7,10.73 42.05,10.73 42.15,10.62 42.15,10.35 v42.3,10.2
  Bottom 0.1: v72.9,7.3 72.28,7.3 71.97,7.6 63,7.6 v62.85,7.45 | v62.85,9.08 62.85,9.28 62.72,9.4 51.88,9.4 51.77,9.5 43.35,9.5 42.62,10.2 v42.3,10.2
DETV  (via drill 1 pad 1.6)
  Top 0.1: BP1. 15.8,7.58 16.9,7.58 16.9,9.33 17.45,9.33 17.45,7.58 17.47,7.58 17.5,8.7
  Top 0.25: 18.07,8.08 18.07,8.12 17.5,8.12 17.5,8.7 17.5,9.3
  other vias: 15.82,8.83
DGND  (via drill 0.05 pad 0.2)
  Top 0: 42.95,5.98 42.55,5.98 | v47.22,11.4 47.2,11.4 | 40.7,18.05 40.72,18.05 | 40.72,18.05 40.77,18.05 | 40.72,18.05 40.62,18.05 | 45.97,1.55 45.82,1.55 | 42.27,12 v42.95,11.12 43,10.98
  Top 0.005: 33.2,17.62 33.17,17.65
  Top 0.075: 61.02,1.53 61.02,1.55 61.02,2.13 v60.92,2.23 | 40.32,18.05 40.32,17.8 40.5,17.62 40.7,17.62 | v55.97,17.48 55.92,17.48 55.52,17.88 55.52,18.05 | v56.27,17.65 56.27,18.05 | 48.07,18.05 48.07,17.77 v48.22,17.62 | 32.72,18.05 32.72,17.83 33.32,17.23 v33.32,17.1 | 33.02,18.05 33.02,17.8 33.17,17.65 | FE-5.5 30.32,17.7 v30,17.38 | 25.12,18.05 25.12,17.77 25.3,17.6 v25.57,17.6 25.57,18.05 | FE-6.5 22.72,17.7 v22.4,17.38 | 33.47,17.62 33.2,17.62 | 33.47,17.62 33.55,17.62 v33.55,17.38 | 33.47,17.62 33.47,18.05 | 17.52,18.05 17.52,17.83 17.82,17.52 17.92,17.52 v18.07,17.38 | 18.27,18.05 18.27,17.68 v18.32,17.62 | FE-8.5 18.27,1.88 v18.62,2.23 | v23.17,1.98 23.17,1.55 | v30.5,2.23 30.55,2.23 30.62,2.15 | 30.62,2.15 30.62,1.55 | 30.92,1.55 30.92,1.85 30.62,2.15 | 38.52,1.55 38.52,1.83 v38.12,2.23 | v37.92,1.95 37.92,1.55 | 45.97,1.55 45.97,1.98 v45.72,2.23 | 53.12,1.55 v53.12,1.98 | v60.72,1.95 60.72,1.55
  Top 0.1: v27.05,10.12 27.7,10.12 | 42.12,9.83 41.7,9.83 | 35.02,5.5 35.02,4.95 | v27.3,7.93 27.7,7.93 | v30.37,10.33 30.4,10.35 | 69.47,12 69.6,12 70.12,12.53 71.42,12.53 71.45,12.5 71.6,12.5 71.8,12.3 | 73.3,12.3 73.15,12.3 73.12,12.28 73.1,12.3 72.75,12.3 | 27.7,11.93 27.35,11.93 27.22,11.8 v27.22,11.53 27.22,11.5 | 35.52,14.1 35.5,14.1 | 35.52,14.12 35.52,14.65 | 63.27,18.05 63.12,18.05 | 63.42,18.05 63.27,18.05 | 63.42,18.05 63.27,18.05 | v71.47,17.62 71.47,18.05 | v71.17,17.48 71.17,18.05 | 70.88,18.05 70.72,18.05 | 71.03,18.05 70.88,18.05 | 71.17,18.05 71.03,18.05 | 71.03,18.05 70.88,18.05 | 71.17,18.05 71.03,18.05 | v63.88,17.65 63.88,18.05 | v63.42,17.65 63.42,18.05 | FE-1.5 60.72,17.73 v60.38,17.38 | v55.97,17.48 55.97,18.05 | 55.52,18.05 55.67,18.05 | v48.67,17.38 48.67,18.05 | 48.07,18.05 47.92,18.05 | FE-4.5 37.92,17.7 v37.6,17.38 | v25.87,17.65 25.87,18.05 | FE-2.5 53.12,17.75 v52.75,17.38 | FE-0.5 68.32,17.75 v67.95,17.38 | FE-3.5 45.52,17.75 v45.15,17.38 | 41.07,18.05 41.07,17.55 v40.9,17.38 | FE-7.5 15.12,17.73 v14.77,17.38 | 15.72,1.55 15.57,1.55 15.42,1.55 v15.42,1.98 | v15.12,2.23 15.12,1.55 | 23.17,1.55 23.32,1.55 | v22.72,1.98 22.72,1.55 | FE-9.5 25.87,1.9 v26.2,2.23 | v30.32,1.98 30.32,1.55 | FE-10.5 33.47,1.9 v33.8,2.23 | v41.7,2.23 41.47,2.23 41.07,1.83 FE-11.5 | v45.52,1.98 45.52,1.55 | FE-12.5 48.67,1.93 v48.97,2.23 | 53.57,1.55 53.57,1.98 v53.32,2.23 | FE-13.5 56.27,1.9 v56.6,2.23 | FE-14.5 63.88,1.88 v64.22,2.23 | v68.32,1.95 68.32,1.55 | FE-15.5 71.47,1.9 v71.8,2.23 | JP2_.5 72.85,2.08 72.72,2.2 v72.53,2.2
  Top 0.15: 40.7,17.62 v40.7,17.65 40.7,17.7
  Top 0.2: 42.12,9.83 42.82,9.83 43,10 43,10.98 | 35.02,5.5 35.02,6.6 34,7.63 34,8.48 32.55,9.93 32.38,9.93 | v29.1,8.15 29.22,8.28 30.55,8.28 32.2,9.93 32.32,9.93 32.38,9.93 | 32.38,9.93 31.97,10.33 v30.37,10.33 | 41.82,2.7 41.82,2.35 v41.7,2.23 | 40.7,17.7 40.7,18.05 | v21.3,2.35 C24. | v28.87,2.35 C26. | v36.47,2.35 C28. | v44.07,2.35 C30. | v51.67,2.35 C32. | v59.27,2.35 C34. | v66.88,2.35 C36.
  Top 0.3: 32.32,9.93 35.52,9.93 35.52,14.1 35.52,14.12
  Top 0.4: 71.53,12.58 71.8,12.3 72.75,12.3 73.28,12.3 | 42.3,3.25 42.3,3.18 41.82,2.7
  Top 0.5: 58.35,7.8 58.35,11.45 58.9,12 | 58.9,12 66.57,12 69.47,12 69.55,12 70.12,12.58 71.53,12.58 | 58.9,12 58.3,12.6 53.8,12.6 52.52,11.33 52.52,11.3 51.15,11.3 48.8,11.3 | 48.8,11.3 47.32,11.3 v47.22,11.4 47.2,11.43 | 42.3,3.25 42.55,3.5 42.95,3.5 42.95,5.98 v42.95,11.12 42.95,11.33 42.27,12 | 35.52,9.93 38.92,9.93 41.02,12.03 42.25,12.03 42.27,12 | 48.8,11.3 48.8,11.48 | v65.32,17.38 C8. | v42.5,17.38 C14. 42.5,16.12 44.97,13.65 v44.97,11.4 | v57.72,17.48 C10. | v50.12,17.48 C12. | v34.92,17.38 C16. | v27.32,17.48 C18. | v19.72,17.48 C20. | R8. 42.45,12.18 42.27,12
  Bottom 0: 71.47,17.38 v71.47,17.62 | v63.88,17.65 63.88,17.38 63.42,17.38 v63.42,17.65 | 44.8,17.38 45.52,17.55 | 40.7,17.38 v40.7,17.65 40.7,17.7 | 55.97,17.38 v55.97,17.48 | 56.27,17.38 v56.27,17.65 | 57.72,17.38 v57.72,17.48 | 50.12,17.38 v50.12,17.48 | 48.22,17.38 v48.22,17.62 | 33.47,17.38 33.47,17.65 | 27.32,17.38 v27.32,17.48 | 25.87,17.38 v25.87,17.65 | 25.57,17.38 v25.57,17.6 | 19.72,17.38 v19.72,17.48 | 71.17,17.38 v71.17,17.48 | 33.32,17.38 33.32,17.23 | v33.55,17.38 33.32,17.38 | 33.32,17.38 v33.32,17.1 | v18.07,17.38 v18.32,17.62 | 15.42,2.23 v15.42,1.98 | 23.17,2.23 v23.17,1.98 | 21.3,2.23 v21.3,2.35 | 22.72,2.23 v22.72,1.98 | 28.87,2.23 v28.87,2.35 | 30.32,2.23 v30.32,1.98 | v30.5,2.23 30.62,1.98 | 36.47,2.23 v36.47,2.35 | 44.07,2.23 v44.07,2.35 | 45.52,2.23 v45.52,1.98 | v51.67,2.35 51.65,2.35 51.65,2.23 | v53.12,1.98 53.12,2.23 | 60.72,2.23 v60.72,1.95 | 59.27,2.23 v59.27,2.35 | 66.88,2.23 v66.88,2.35 | 68.32,2.23 v68.32,1.95 | 37.92,2.23 v37.92,1.95
  Bottom 0.1: v27.3,7.93 28.87,7.93 v29.1,8.15 | v30.37,10.33 27.25,10.33 v27.05,10.12 27.22,10.3 v27.22,11.53 | v71.8,2.23 72.5,2.23 v72.53,2.2
  Bottom 0.5: v47.22,11.4 v44.97,11.4 43.22,11.4 v42.95,11.12
  Bottom 0.75: 14.37,17.38 v14.77,17.38 v18.07,17.38 19.72,17.38 v22.4,17.38 25.57,17.38 25.87,17.38 27.32,17.38 v30,17.38 33.32,17.38 33.47,17.38 v33.55,17.38 v34.92,17.38 v37.6,17.38 40.7,17.38 v40.9,17.38 v42.5,17.38 44.8,17.38 v45.15,17.38 48.22,17.38 v48.67,17.38 50.12,17.38 v52.75,17.38 55.97,17.38 56.27,17.38 57.72,17.38 v60.38,17.38 63.88,17.38 v65.32,17.38 v67.95,17.38 71.17,17.38 71.47,17.38 | 71.85,2.23 v71.8,2.23 68.32,2.23 66.88,2.23 v64.22,2.23 v60.92,2.23 60.72,2.23 59.27,2.23 v56.6,2.23 v53.32,2.23 53.12,2.23 51.65,2.23 v48.97,2.23 v45.72,2.23 45.52,2.23 44.07,2.23 v41.7,2.23 v38.12,2.23 37.92,2.23 36.47,2.23 v33.8,2.23 v30.5,2.23 30.32,2.23 28.87,2.23 v26.2,2.23 23.17,2.23 22.72,2.23 21.3,2.23 v18.62,2.23 15.42,2.23 v15.12,2.23 14.57,2.23
DTO0N  (via drill 0.05 pad 0.2)
  Top 0.1: 73.3,9.3 72.75,9.3 v72.72,9.33 | v60.85,8.68 60.85,7.8 | BARE_DIE.N v42.1,9.18 | R3. 71.53,10.08 71.65,9.95 71.65,9.75 v72.07,9.33
  Bottom 0.1: v42.1,9.18 42.72,9.18 43,8.9 51.07,8.9 51.17,8.8 60.72,8.8 v60.85,8.68 60.9,8.62 71.3,8.62 72,9.33 v72.07,9.33 v72.72,9.33
DTO0P  (via drill 0.05 pad 0.2)
  Top 0.1: v72.72,9.8 73.3,9.8 | v61.35,8.88 61.35,7.8 | BARE_DIE.P v41.22,9.33 | 69.3,11.18 69.78,11.18 70.5,10.45 71.85,10.45 72.05,10.25 v72.05,9.8
  Bottom 0.1: v72.72,9.8 v72.05,9.8 71.07,8.83 61.4,8.83 v61.35,8.88 61.22,9 51.42,9 51.32,9.1 43.1,9.1 42.77,9.43 41.32,9.43 v41.22,9.33
FE-0N  (via drill 0.05 pad 0.2)
  Top 0.075: BARE_DIE.0N 37.02,14.55 | 70.28,16.93 69.97,17.23 69.97,18.05
  Top 0.1: 37.02,14.55 v37.02,13.2 | v70.28,13.2 70.28,16.93
  Bottom 0.1: v37.02,13.2 v70.28,13.2
FE-0P  (via drill 0.05 pad 0.2)
  Top 0.075: 70.03,16.83 69.82,17.02 69.82,18.05
  Top 0.1: BARE_DIE.0P 36.67,14.55 v36.67,12.95 | 70.03,16.83 70.03,13.88 69.7,13.55 v69.7,12.95
  Bottom 0.1: v36.67,12.95 37.27,12.95 37.32,13 69.65,13 v69.7,12.95
FE-1N  (via drill 0.05 pad 0.2)
  Top 0.075: 62.67,16.93 62.38,17.23 62.38,18.05
  Top 0.1: BARE_DIE.1N 36.32,14.55 v36.32,12.7 | v62.82,12.7 62.67,12.85 62.67,16.93
  Bottom 0.1: v36.32,12.7 37.38,12.7 37.47,12.8 62.72,12.8 v62.82,12.7
FE-1P  (via drill 0.05 pad 0.2)
  Top 0.075: 62.42,16.83 62.22,17.02 62.22,18.05
  Top 0.1: BARE_DIE.1P 35.97,14.55 v35.97,12.45 | v62.42,12.53 62.42,16.83
  Bottom 0.1: v35.97,12.45 37.42,12.45 37.57,12.6 62.35,12.6 v62.42,12.53
FE-2N  (via drill 0.05 pad 0.2)
  Top 0.075: 55.07,16.93 54.77,17.23 54.77,18.05
  Top 0.1: BARE_DIE.2N 34.52,14.55 v34.52,13.2 | v52.7,12.35 52.7,12.93 52.88,13.1 54.88,13.1 55.07,13.3 55.07,16.93
  Bottom 0.1: v52.7,12.35 52.7,12.4 37.72,12.4 37.52,12.2 35.52,12.2 v34.52,13.2
FE-2P  (via drill 0.05 pad 0.2)
  Top 0.075: 54.82,16.83 54.62,17.02 | 54.62,17.02 54.62,17 | 54.62,17.02 54.62,18.05
  Top 0.1: v52.35,12.15 52.35,13.12 52.55,13.33 54.65,13.33 54.82,13.5 54.82,16.83 | v34.22,13.05 34.27,13.1 BARE_DIE.2P
  Bottom 0.1: v52.35,12.15 52.35,12.2 37.85,12.2 37.65,12 35.27,12 v34.22,13.05
FE-3N  (via drill 0.05 pad 0.2)
  Top 0.075: 47.47,16.93 47.17,17.23 47.17,18.05
  Top 0.1: BARE_DIE.3N 33.77,14.6 33.77,14.38 33.75,14.35 v33.75,13.2 | v48.17,11.95 48.17,12.95 47.47,13.65 47.47,16.93
  Bottom 0.1: v48.17,11.95 48.17,12 37.97,12 37.77,11.8 35,11.8 33.75,13.05 v33.75,13.2
FE-3P  (via drill 0.05 pad 0.2)
  Top 0.075: 47.22,16.83 47.02,17.02 47.02,18.05
  Top 0.1: BARE_DIE.3P 33.5,14.58 33.5,14 33.55,13.95 33.55,13.53 33.4,13.38 v33.4,13.12 | 47.22,16.83 47.22,13.33 47.82,12.73 v47.82,11.75
  Bottom 0.1: v47.82,11.75 47.82,11.8 38.12,11.8 37.92,11.6 34.77,11.6 33.4,12.98 v33.4,13.12
FE-4N  (via drill 0.05 pad 0.2)
  Top 0.075: 39.88,16.93 39.57,17.23 39.57,18.05
  Top 0.1: BARE_DIE.4N 33.07,14.6 33.07,13.9 33.05,13.88 v33.05,13.2 | 39.88,16.93 39.88,13.7 39.57,13.4 39.25,13.4 39.12,13.28 v39.12,11.55
  Bottom 0.1: v33.05,13.2 33.05,12.98 34.62,11.4 38.05,11.4 38.22,11.58 39.1,11.58 39.1,11.55 v39.12,11.55
FE-4P  (via drill 0.05 pad 0.2)
  Top 0.075: 39.62,16.83 39.42,17.02 39.42,18.05
  Top 0.1: v32.75,12.93 32.75,13.7 32.82,13.78 32.82,14.6 BARE_DIE.4P | 39.62,16.83 39.62,13.78 39.47,13.62 39,13.62 38.8,13.43 v38.8,11.33
  Bottom 0.1: v32.75,12.93 34.47,11.2 38.27,11.2 38.4,11.33 v38.8,11.33
FE-5N
  Top 0.075: 32.27,16.93 31.97,17.23 31.97,18.05
  Top 0.1: BARE_DIE.5N 32.42,14.75 32.42,15.55 32.27,15.7 32.27,16.93
FE-5P
  Top 0.075: 32.02,16.83 31.82,17.02 31.82,18.05
  Top 0.1: BARE_DIE.5P 32.15,14.68 32.15,15.28 32.02,15.4 32.02,16.83
FE-6N  (via drill 0.05 pad 0.2)
  Top 0.075: 24.67,16.93 24.37,17.23 24.37,18.05
  Top 0.1: BARE_DIE.6N 31.67,14.6 v31.67,12.45 | v26.22,12.45 26.07,12.6 26.07,13.05 26.02,13.1 25.97,13.1 24.67,14.4 24.67,16.93
  Bottom 0.1: v26.22,12.45 26.6,12.45 26.75,12.6 30.22,12.6 30.37,12.45 v31.67,12.45
FE-6P  (via drill 0.05 pad 0.2)
  Top 0.075: 24.42,16.83 24.22,17.02 24.22,18.05
  Top 0.1: BARE_DIE.6P 31.45,14.62 31.45,14.3 31.35,14.2 v31.35,12.7 | 24.42,16.83 24.42,14.3 24.77,13.95 24.77,13.88 25.6,13.05 v25.6,12.6
  Bottom 0.1: v25.6,12.6 25.8,12.8 30.4,12.8 30.5,12.7 v31.35,12.7
FE-7N  (via drill 0.05 pad 0.2)
  Top 0.075: 17.07,16.93 16.77,17.23 16.77,18.05
  Top 0.1: BARE_DIE.7N 30.95,14.62 v30.95,12.95 | v17.07,12.95 17.07,16.93
  Bottom 0.1: v17.07,12.95 25.47,12.95 25.47,13 30.5,13 30.55,12.95 v30.95,12.95
FE-7P  (via drill 0.05 pad 0.2)
  Top 0.075: 16.82,16.83 16.62,17.02 16.62,18.05
  Top 0.1: v30.67,13.2 30.67,14.55 BARE_DIE.7P | v16.82,13.2 16.82,16.83
  Bottom 0.1: v30.67,13.2 v16.82,13.2
FE-8N  (via drill 0.05 pad 0.2)
  Top 0.075: 16.32,2.68 16.62,2.38 16.62,1.55
  Top 0.1: BARE_DIE.8N 30.72,5.05 v30.72,6.4 | v15.05,4.43 16.2,4.43 16.32,4.3 16.32,2.68
  Bottom 0.1: v30.72,6.4 28.32,6.4 28.27,6.35 23.55,6.35 23.5,6.4 22.77,6.4 22.75,6.38 15.42,6.38 15.05,6 v15.05,4.43
FE-8P  (via drill 0.05 pad 0.2)
  Top 0.075: 16.57,2.78 16.77,2.58 16.77,1.55
  Top 0.1: BARE_DIE.8P 30.97,5.63 31.1,5.75 v31.1,6.65 | v14.72,4.75 16.45,4.75 16.57,4.63 16.57,2.78
  Bottom 0.1: v31.1,6.65 28.2,6.65 28.1,6.55 23.7,6.55 23.65,6.6 22.62,6.6 22.6,6.58 14.72,6.58 v14.72,4.75
FE-9N  (via drill 0.05 pad 0.2)
  Top 0.075: 23.92,2.68 24.22,2.38 24.22,1.55
  Top 0.1: v23.92,7.18 23.92,2.68 | v31.47,7.15 31.47,5 BARE_DIE.9N
  Bottom 0.1: v31.47,7.15 31.47,7.1 27.82,7.1 27.72,7 24.67,7 24.5,7.18 v23.92,7.18
FE-9P  (via drill 0.05 pad 0.2)
  Top 0.075: 24.17,2.78 24.37,2.58 24.37,1.55
  Top 0.1: BARE_DIE.9P 31.67,5.3 31.8,5.43 v31.8,6.9 | v24.17,6.83 24.17,2.78
  Bottom 0.1: v31.8,6.9 28.05,6.9 27.9,6.75 24.5,6.75 24.42,6.83 v24.17,6.83
FE-10N  (via drill 0.05 pad 0.2)
  Top 0.075: 31.52,2.68 31.82,2.38 31.82,1.55
  Top 0.1: v30,7.65 30,4.78 31.52,3.25 31.52,2.68 | BARE_DIE.10N 32.17,5 v32.17,7.65
  Bottom 0.1: v32.17,7.65 v30,7.65
FE-10P  (via drill 0.05 pad 0.2)
  Top 0.075: 31.77,2.78 31.97,2.58 31.97,1.55
  Top 0.1: BARE_DIE.10P 32.38,4.98 32.52,5.13 v32.52,7.4 | v30.35,7.4 30.35,4.78 31.77,3.35 31.77,2.78
  Bottom 0.1: v32.52,7.4 v30.35,7.4
FE-11N  (via drill 0.05 pad 0.2)
  Top 0.075: 39.12,2.68 39.42,2.38 39.42,1.55
  Top 0.1: v32.8,7.18 32.8,5.15 32.92,5.03 BARE_DIE.11N | v38.88,8.3 38.88,5.93 39.12,5.68 39.12,2.68
  Bottom 0.1: v38.88,8.3 38.82,8.25 33.88,8.25 v32.8,7.18
FE-11P  (via drill 0.05 pad 0.2)
  Top 0.075: 39.38,2.78 39.57,2.58 39.57,1.55
  Top 0.1: v33.22,7.08 33.22,5.18 33.07,5.03 BARE_DIE.11P | v39.12,8.05 39.22,7.95 39.22,5.93 39.38,5.78 39.38,2.78
  Bottom 0.1: v33.22,7.08 34.2,8.05 v39.12,8.05
FE-12N  (via drill 0.05 pad 0.2)
  Top 0.075: 46.72,2.68 47.02,2.38 47.02,1.55
  Top 0.1: v46.72,7.85 46.72,2.68 | v33.5,6.88 33.5,5.08 BARE_DIE.12N
  Bottom 0.1: v46.72,7.85 46.72,7.8 38.9,7.8 38.85,7.85 34.45,7.85 34.45,7.83 v33.5,6.88
FE-12P  (via drill 0.05 pad 0.2)
  Top 0.075: 46.97,2.78 47.17,2.58 47.17,1.55
  Top 0.1: v46.97,7.65 46.97,2.78 | v33.88,6.73 33.88,5.05 BARE_DIE.12P
  Bottom 0.1: v46.97,7.65 46.97,7.6 38.77,7.6 38.72,7.65 34.8,7.65 v33.88,6.73
FE-13N  (via drill 0.05 pad 0.2)
  Top 0.075: 54.32,2.68 54.62,2.38 54.62,1.55
  Top 0.1: 54.32,2.68 54.32,5.58 53.88,6.03 53.57,6.03 52.15,7.45 v52.07,7.45 | v34.22,6.53 34.22,5.05 BARE_DIE.13N
  Bottom 0.1: v52.07,7.45 52.07,7.4 38.67,7.4 38.62,7.45 35.15,7.45 35.07,7.38 | 35.07,7.38 v34.22,6.53 | 35.07,7.38 35.1,7.4
FE-13P  (via drill 0.05 pad 0.2)
  Top 0.075: 54.22,6.05 54.22,6.03 | 54.57,2.78 54.77,2.58 54.77,1.55
  Top 0.1: 54.57,2.78 54.57,5.7 54.22,6.05 53.02,7.25 v52.77,7.25 | v34.57,6.4 34.57,5.05 BARE_DIE.13P
  Bottom 0.1: v52.77,7.25 52.77,7.2 38.57,7.2 38.52,7.25 35.42,7.25 v34.57,6.4
FE-14N  (via drill 0.05 pad 0.2)
  Top 0.075: 61.92,2.68 62.22,2.38 62.22,1.55
  Top 0.1: v64.67,7.05 64.67,6.95 64.55,6.83 63.22,6.83 62.88,6.48 62.35,6.48 61.92,6.05 61.92,2.68 | v36.02,6.55 36.02,5.05 BARE_DIE.14N
  Bottom 0.1: v64.67,7.05 64.67,7 38.47,7 38.42,7.05 36.15,7.05 36.02,6.93 v36.02,6.55
FE-14P  (via drill 0.05 pad 0.2)
  Top 0.075: 62.17,2.78 62.38,2.58 62.38,1.55
  Top 0.1: v65.3,6.85 65.3,6.75 65.17,6.63 63.38,6.63 62.97,6.23 62.45,6.23 62.17,5.95 62.17,2.78 | v36.38,6.55 36.38,5.05 BARE_DIE.14P
  Bottom 0.1: v65.3,6.85 65.3,6.8 38.27,6.8 38.22,6.85 36.5,6.85 36.38,6.73 v36.38,6.55
FE-15N  (via drill 0.05 pad 0.2)
  Top 0.075: 69.53,2.68 69.82,2.38 69.82,1.55
  Top 0.1: v69.53,6.65 69.53,2.68 | v36.7,6.4 36.7,5.08 BARE_DIE.15N
  Bottom 0.1: v69.53,6.65 69.53,6.6 38.07,6.6 38.02,6.65 36.8,6.65 36.7,6.55 v36.7,6.4
FE-15P  (via drill 0.05 pad 0.2)
  Top 0.075: 69.78,2.78 69.97,2.58 69.97,1.55
  Top 0.1: v37,6.4 37,6.08 37.05,6.03 37.05,5.03 BARE_DIE.15P | v69.78,6.4 69.78,2.78
  Bottom 0.1: v37,6.4 v69.78,6.4
HV_GUARD  (via drill 0.05 pad 0.2)
  Top 0: C4. 18.1,5.3 20.45,5.3
  Top 0.1: 23,7.28 23,8.1 | 23,7.28 22.45,7.28 20.47,5.3 20.45,5.3 13.95,5.3 13.95,10.65 23.9,10.65 v23.9,7.63 23.55,7.28 23,7.28 | v27,7.63 R6. 27.47,6.33 27.7,6.1 R9.
  Bottom 0.1: v23.9,7.63 23.92,7.65 23.95,7.63 v27,7.63
LD  (via drill 0.05 pad 0.2)
  Top 0.075: 17.32,17.02 16.92,17.43 16.92,18.05 | 24.92,17.02 24.52,17.43 24.52,18.05 | 32.52,17.02 32.12,17.43 32.12,18.05 | 40.12,17.02 39.72,17.43 39.72,18.05 | 47.72,17.02 47.32,17.43 47.32,18.05 | 55.32,17.02 54.92,17.43 54.92,18.05 | 62.92,17.02 62.52,17.43 62.52,18.05 | 70.53,17.02 70.12,17.43 70.12,18.05 | 16.07,2.58 16.47,2.18 16.47,1.55 | 23.67,2.58 24.07,2.18 24.07,1.55 | 31.27,2.58 31.67,2.18 31.67,1.55 | 38.88,2.58 39.27,2.18 39.27,1.55 | 54.07,2.58 54.47,2.18 54.47,1.55 | 61.67,2.58 62.07,2.18 62.07,1.55 | 69.28,2.58 69.67,2.18 69.67,1.55 | 46.47,2.58 46.88,2.18 46.88,1.55
  Top 0.1: v29.67,5.65 29.67,4.78 31.27,3.18 31.27,2.58 | v72.9,5.08 73.3,5.08 | v19.3,13.95 R11. | v17.32,13.95 17.32,17.02 | 24.92,17.02 24.92,14.65 25.17,14.4 25.3,14.4 25.52,14.18 v25.52,13.95 | 32.52,17.02 32.52,15.8 32.62,15.7 32.62,14.2 v32.38,13.95 | v40.12,13.95 40.12,17.02 | v47.72,13.95 47.72,17.02 | v55.32,13.95 55.32,17.02 | v62.92,13.95 62.92,17.02 | v70.53,13.95 70.53,17.02 | v16.07,3.93 16.07,2.58 | v23.67,5.65 23.67,2.58 | 38.88,2.58 38.88,5.5 v38.72,5.65 | 54.07,2.58 54.07,5.45 v53.88,5.65 | v61.67,5.65 61.67,2.58 | v69.28,5.65 69.28,2.58 | v46.47,5.65 46.47,2.58
  Bottom 0.1: v70.53,13.95 v62.92,13.95 v55.32,13.95 v47.72,13.95 v40.12,13.95 v32.38,13.95 v25.52,13.95 v19.3,13.95 v17.32,13.95 14.72,13.95 14.05,13.28 14.05,4.03 14.47,3.6 15.75,3.6 v16.07,3.93 16.07,5.43 16.3,5.65 v23.67,5.65 v29.67,5.65 v38.72,5.65 v46.47,5.65 v53.88,5.65 v61.67,5.65 v69.28,5.65 71.8,5.65 72.38,5.08 v72.9,5.08
LV1N  (via drill 0.05 pad 0.2)
  Top 0: v26.8,15.2 26.8,14.5 26.87,14.45
  Top 0.075: 15.57,16.73 15.87,17.02 FE-7.0 | 23.17,16.73 23.47,17.02 FE-6.0 | 30.77,16.73 31.07,17.02 FE-5.0 | 38.38,16.73 38.67,17.02 FE-4.0 | 45.97,16.73 46.27,17.02 FE-3.0 | 53.57,16.73 53.88,17.02 FE-2.0 | 61.17,16.73 61.47,17.02 FE-1.0 | 68.78,16.73 69.07,17.02 FE-0.0 | 17.82,2.88 17.52,2.58 FE-8.0 | 25.42,2.88 25.12,2.58 FE-9.0 | 33.02,2.88 32.72,2.58 FE-10.0 | 40.62,2.88 40.32,2.58 FE-11.0 | 55.82,2.88 55.52,2.58 FE-13.0 | 63.42,2.88 63.12,2.58 FE-14.0 | 71.03,2.88 70.72,2.58 FE-15.0 | 48.22,2.88 47.92,2.58 FE-12.0
  Top 0.1: 27.7,11.18 27.6,11.28 26.8,11.28 | 26.8,11.28 26.47,11.28 25.42,10.23 v25.42,4.4 25.42,2.88 | 26.8,11.28 v26.8,15.2 | v15.57,15.2 15.57,16.73 | v23.17,15.2 23.17,16.73 | v29.7,15.2 29.7,15.45 30.77,16.52 30.77,16.73 | v38.38,15.2 38.38,16.73 | v45.97,15.2 45.97,16.73 | v53.57,15.2 53.57,16.73 | v61.17,15.2 61.17,16.73 | v68.78,15.2 68.78,16.73 | 17.82,2.88 17.82,3.68 v18.05,3.9 | 33.02,2.88 33.02,4 33.42,4.4 v33.5,4.4 | v40.62,4.4 40.62,2.88 | 55.82,2.88 v55.82,4.4 | v63.42,4.4 63.42,2.88 | 71.03,2.88 v71.03,4.4 72.03,4.4 72.85,3.58 73.3,3.58 | v48.22,4.4 48.22,2.88
  Bottom 0.1: v71.03,4.4 v63.42,4.4 v55.82,4.4 v48.22,4.4 v40.62,4.4 v33.5,4.4 v25.42,4.4 18.55,4.4 v18.05,3.9 | v15.57,15.2 v23.17,15.2 v26.8,15.2 v29.7,15.2 v38.38,15.2 v45.97,15.2 v53.57,15.2 v61.17,15.2 v68.78,15.2
LV1P  (via drill 0.05 pad 0.2)
  Top 0: v28.17,15.45 28.17,14.62 R14.
  Top 0.075: 15.32,16.83 15.72,17.23 FE-7.1 | 22.92,16.83 23.32,17.23 FE-6.1 | 30.52,16.83 30.92,17.23 FE-5.1 | 38.12,16.83 38.52,17.23 FE-4.1 | 45.72,16.83 46.12,17.23 FE-3.1 | 53.32,16.83 53.72,17.23 FE-2.1 | 60.92,16.83 61.32,17.23 FE-1.1 | 68.53,16.83 68.92,17.23 FE-0.1 | 18.07,2.78 17.67,2.38 FE-8.1 | 25.67,2.78 25.27,2.38 FE-9.1 | 33.27,2.78 32.88,2.38 FE-10.1 | 40.88,2.78 40.47,2.38 FE-11.1 | 56.07,2.78 55.67,2.38 FE-13.1 | 63.67,2.78 63.27,2.38 FE-14.1 | 71.28,2.78 70.88,2.38 FE-15.1 | 48.47,2.78 48.07,2.38 FE-12.1
  Top 0.1: v28.17,15.45 28.17,11.03 27.7,11.03 26.7,11.03 25.67,10 v25.67,4.15 25.67,2.78 | v15.32,15.45 15.32,16.83 | v22.92,15.45 22.92,16.83 | v29.35,15.45 29.35,15.65 30.52,16.83 | v38.12,15.45 38.12,16.83 | v45.72,15.45 45.72,16.83 | v53.32,15.45 53.32,16.83 | v60.92,15.45 60.92,16.83 | v68.53,15.45 68.53,16.83 | 18.07,2.78 18.07,3.55 v18.42,3.9 | v33.72,4.15 33.65,4.15 33.27,3.78 33.27,2.78 | v40.88,4.15 40.88,2.78 | v56.07,4.15 56.07,2.78 | v63.67,4.15 63.67,2.78 | 71.28,2.78 v71.28,4.15 71.95,4.15 72.82,3.28 73.3,3.28 | v48.47,4.15 48.47,2.78
  Bottom 0.1: v15.32,15.45 v22.92,15.45 v28.17,15.45 v29.35,15.45 v38.12,15.45 v45.72,15.45 v53.32,15.45 v60.92,15.45 v68.53,15.45 | v18.42,3.9 18.67,4.15 v25.67,4.15 v33.72,4.15 v40.88,4.15 v48.47,4.15 v56.07,4.15 v63.67,4.15 v71.28,4.15
N$1
  Top 0.1: 29.05,7.1 29.05,6.5 29.77,6.5
N$2
  Top 0.1: 77.95,8.8 80.12,8.8 84.7,13.38 85.6,13.38
N$3
  Top 0.1: 39.6,6.5 40.35,6.5 40.35,7.1
N$4
  Top 0.1: 85.6,9.48 84.7,9.48 80.9,5.68 77.95,5.68
N$5
  Top 0.1: 85.6,8.83 84.7,8.83 81.25,5.38 77.95,5.38
N$6
  Top 0.1: 85.6,8.18 84.7,8.18 81.6,5.08 77.95,5.08
N$7
  Top 0.2: 77.95,11.3 78.7,11.3
  Top 0.5: 85.6,16.62 84.22,16.62 83.45,15.85 | 81.03,13.43 81.03,12.93 79.4,11.3 78.7,11.3
  Top 1: 81.03,13.43 83.45,15.85
N$8
  Top 0.1: 85.6,7.53 84.7,7.53 81.95,4.78 77.95,4.78
N$9
  Top 0.1: 85.6,6.88 84.7,6.88 82.3,4.48 77.95,4.48
N$10
  Top 0.1: JPA_.2 80.28,8.3 84.7,12.73 85.6,12.73
N$11
  Top 0.1: 85.6,6.23 84.7,6.23 82.65,4.18 77.95,4.18
N$12
  Top 0.1: 85.6,5.58 84.7,5.58 83,3.88 77.95,3.88
N$13
  Top 0.1: 85.6,4.93 84.7,4.93 83.35,3.58 77.95,3.58
N$14
  Top 0.1: JPA_.6 80.57,7.3 84.7,11.43 85.6,11.43
N$15
  Top 0.1: JPA_.4 80.42,7.8 84.7,12.08 85.6,12.08
N$16
  Top 0.1: 77.95,9.8 79.82,9.8 84.7,14.68 85.6,14.68
N$17
  Top 0.1: 77.95,9.3 79.97,9.3 84.7,14.03 85.6,14.03
N$18
  Top 0.1: JPA_.8 80.72,6.8 84.7,10.78 85.6,10.78
N$19
  Top 0.1: JPA_.0 80.88,6.3 84.7,10.12 85.6,10.12
N$20
  Top 0.1: 77.95,10.3 79.67,10.3 84.7,15.33 85.6,15.33
N$21
  Top 0.1: 85.6,19.23 81.45,19.23 77.92,15.7 77.92,13.33 77.95,13.3
N$22  (via drill 0.05 pad 0.2)
  Top 0.2: 77.95,12.8 v78.95,12.8
  Top 0.5: v84.65,18.58 85.6,18.58
  Bottom 1: v84.65,18.58 84.65,18.5 83.1,18.5 78.95,14.35 v78.95,12.8
N$23  (via drill 0.05 pad 0.2)
  Top 0.2: 77.95,11.8 v78.85,11.8
  Top 0.5: v84.6,17.27 85.6,17.27
  Bottom 0.2: v78.85,11.8 79.8,11.8
  Bottom 1: v84.6,17.27 83.72,17.27 80.3,13.85 80.3,12.3 79.8,11.8
N$24
  Top 0.2: 79.72,12.85 79.17,12.3 77.95,12.3
  Top 0.5: 83.45,17.93 85.6,17.93
  Top 1: 83.45,17.93 79.72,14.2 79.72,12.85
N$25
  Top 0.1: 77.95,10.8 79.53,10.8 84.7,15.98 85.6,15.98
N$26
  Top 0.1: 85.6,4.28 84.7,4.28 83.7,3.28 77.95,3.28
N$27
  Top 0.1: 85.6,3.63 84.7,3.63 84.05,2.98 77.95,2.98
N$28
  Top 0.1: 85.6,2.98 84.7,2.98 84.4,2.68 JP2_.2
N$29
  Top 0.1: JP2_.6 84.38,2.08 84.78,1.68 85.6,1.68
N$30
  Top 0.1: JP2_.8 84.12,1.78 84.85,1.05 85.22,1.05 85.25,1.03 85.6,1.03
N$31  (via drill 0.05 pad 0.2)
  Top 0.1: 37.47,14.65 37.47,14.03 38.52,12.98 v38.52,11.03 | v22.4,12.05 22.4,12.33
  Bottom 0.1: v38.52,11.03 38.4,11.03 38.38,11 34.38,11 33.17,12.2 30.3,12.2 30.15,12.35 26.87,12.35 26.7,12.18 24.65,12.18 24.47,12.35 22.7,12.35 v22.4,12.05
N$32
  Top 0.1: 85.6,2.33 84.67,2.33 84.62,2.38 JP2_.4
N$33
  Top 0.1: JP2_.0 83.75,1.48 84.85,0.38 CN_T.
N$34  (via drill 0.05 pad 0.2)
  Top 0.1: 37.52,4.95 37.52,6.28 38.42,7.18 v38.42,9.23 | v19.3,12.33 19.3,12.58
